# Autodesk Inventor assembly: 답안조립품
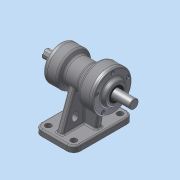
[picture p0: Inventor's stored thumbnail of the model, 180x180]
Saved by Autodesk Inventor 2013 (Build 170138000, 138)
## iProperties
Created: 2015-08
Part Number: 답안조립품
Document SubType Name: Assembly
Designer: Administrator
Author: Administrator
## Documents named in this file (10)
- C:\Users\Administrator\Desktop\450806V1019\답안조립품.iam
- C:\Users\Administrator\Desktop\450806V1019\본체.ipt
- C:\Users\Administrator\Desktop\450806V1019\M4x0.5.ipt
- C:\Users\Administrator\Desktop\450806V1019\뒤커버.ipt
- C:\Users\Administrator\Desktop\450806V1019\베어링 6203.ipt
- C:\Users\Administrator\Desktop\450806V1019\베어링 6205.ipt
- C:\Users\Administrator\Desktop\450806V1019\앞커버.ipt
- C:\Users\Administrator\Desktop\450806V1019\오일실 .ipt
- 오일실 .ipt
- C:\Users\Administrator\Desktop\450806V1019\축.ipt
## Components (10 placed, 1 different names)
1. M4x0.5:1
2. M4x0.5:3
3. M4x0.5:4
4. M4x0.5:5
5. M4x0.5:6
6. M4x0.5:2
7. M4x0.5:7
8. M4x0.5:8
9. M4x0.5:9
10. M4x0.5:10
